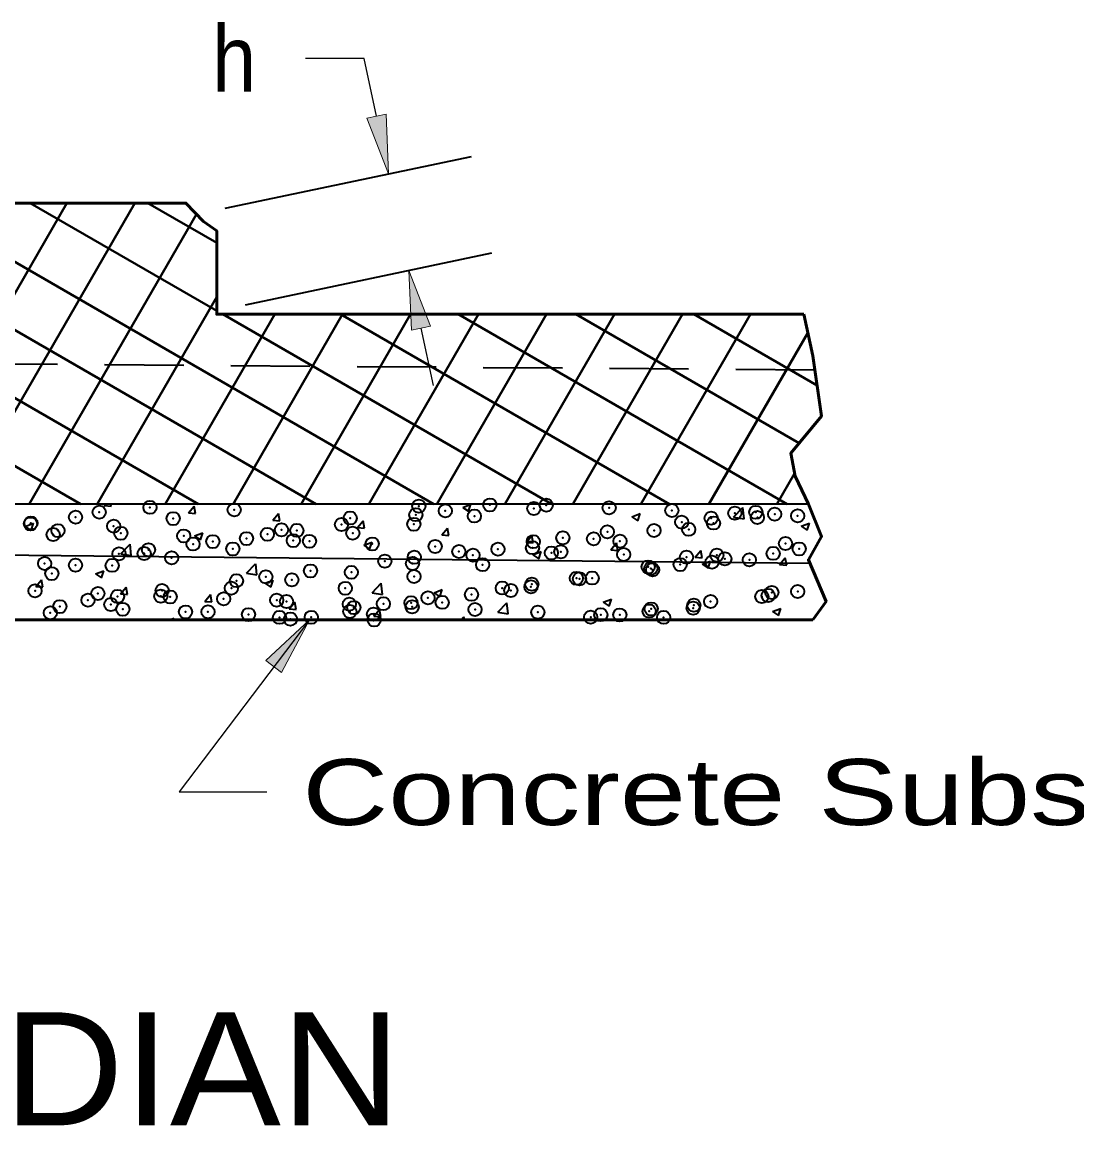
# Model space of a CAD drawing. Extents: x 14 to 49.3, y 28 to 50.
# Drawn here: x 22.139 to 24.379, y 39.449 to 41.795 of the extents above; entities that cross this region are included whole.
import ezdxf

# ---------------------------------------------------------------- set-up
doc = ezdxf.new("R2010")
doc.units = 0
doc.header["$LTSCALE"] = 0.056
doc.header["$PDMODE"] = 32
doc.header["$PDSIZE"] = 0.028
doc.linetypes.add('MEDIUM_DASHED', pattern=[4.5, 3, -1.5])
for name, color, linetype, lineweight in [('1', 7, 'Continuous', 35), ('2', 7, 'MEDIUM_DASHED', 35), ('3', 7, 'Continuous', 13), ('6', 7, 'Continuous', 13)]:
    doc.layers.add(name, color=color, linetype=linetype, lineweight=lineweight)

msp = doc.modelspace()

# ---------------------------------------------------------------- hatches: boundary and pattern name
at = {"layer": '1'}
for points in [[(22.87092, 41.59092), (22.91167, 41.5995), (22.917, 41.47283), (22.917, 41.47283)], [(22.9655, 41.14108), (23.00625, 41.14967), (22.96017, 41.26767), (22.96017, 41.26767)]]:
    msp.add_hatch(color=256, dxfattribs=at).paths.add_polyline_path(points)
at = {"layer": '3'}
msp.add_hatch(color=256, dxfattribs=at).paths.add_polyline_path([(22.65642, 40.43917), (22.68958, 40.41375), (22.749, 40.52558), (22.749, 40.52558)])

# ---------------------------------------------------------------- linework, layer by layer
at = {"layer": '1', "lineweight": 25}
for p, q in [((22.86558, 41.7175), (22.74058, 41.7175)), ((22.89125, 41.59517), (22.86558, 41.7175)), ((22.98583, 41.14533), (23.01158, 41.02308))]:
    msp.add_line(p, q, dxfattribs=at)
at = {"layer": '1'}
for p, q in [((22.57042, 41.4), (23.09317, 41.50992)), ((22.6135, 41.19483), (23.13625, 41.30475)), ((23.80842, 40.77142), (18.85933, 40.77142)), ((22.31292, 40.76875), (22.31517, 40.77142)), ((22.32783, 40.76742), (22.32708, 40.77142)), ((23.0745, 40.76458), (23.092, 40.77133)), ((23.08692, 40.75625), (23.092, 40.77133)), ((22.31292, 40.76875), (22.32783, 40.76742)), ((22.49217, 40.75308), (22.50425, 40.76742)), ((22.49217, 40.75308), (22.50717, 40.75175)), ((22.50717, 40.75175), (22.50425, 40.76742)), ((22.6715, 40.73742), (22.68358, 40.75175)), ((22.6865, 40.73608), (22.68358, 40.75175)), ((23.0745, 40.76458), (23.08692, 40.75625)), ((23.43375, 40.74458), (23.45125, 40.75133)), ((23.44617, 40.73617), (23.45125, 40.75133)), ((23.6495, 40.744), (23.669, 40.76433)), ((23.67175, 40.74058), (23.669, 40.76425)), ((22.14583, 40.724), (22.16333, 40.73075)), ((22.14583, 40.724), (22.15825, 40.71567)), ((22.15833, 40.71558), (22.16333, 40.73075)), ((22.6715, 40.73742), (22.68642, 40.73608)), ((22.85083, 40.72167), (22.86283, 40.73608)), ((22.86575, 40.72042), (22.86292, 40.73608)), ((23.43375, 40.74458), (23.44617, 40.73617)), ((23.6495, 40.744), (23.67175, 40.74058)), ((23.793, 40.72458), (23.8105, 40.73125)), ((23.793, 40.72458), (23.8055, 40.71617)), ((23.8055, 40.71617), (23.81058, 40.73125)), ((22.50517, 40.704), (22.52267, 40.71075)), ((22.50517, 40.704), (22.51758, 40.69558)), ((22.51758, 40.69558), (22.52267, 40.71067)), ((22.85083, 40.72167), (22.86575, 40.72042)), ((23.03017, 40.706), (23.04217, 40.72033)), ((23.03017, 40.706), (23.04508, 40.70467)), ((23.04508, 40.70467), (23.04217, 40.72033)), ((23.20942, 40.69033), (23.2215, 40.70467)), ((23.22442, 40.689), (23.2215, 40.70467)), ((23.81192, 40.64508), (18.81242, 40.69783)), ((22.34858, 40.666), (22.36808, 40.68625)), ((22.37083, 40.6625), (22.36808, 40.68625)), ((22.86442, 40.684), (22.88192, 40.69067)), ((22.86442, 40.684), (22.87683, 40.67558)), ((22.87683, 40.67558), (22.88192, 40.69067)), ((23.20942, 40.69033), (23.22442, 40.689)), ((23.20942, 40.69033), (23.22442, 40.689)), ((23.38875, 40.67467), (23.40083, 40.689)), ((23.40375, 40.67333), (23.40083, 40.689)), ((22.34858, 40.666), (22.37083, 40.66258)), ((23.22367, 40.66392), (23.24117, 40.67067)), ((23.22367, 40.66392), (23.23617, 40.65558)), ((23.23617, 40.65558), (23.24125, 40.67067)), ((23.38875, 40.67467), (23.40375, 40.67333)), ((23.56808, 40.65892), (23.58017, 40.67333)), ((23.56808, 40.65892), (23.583, 40.65767)), ((23.583, 40.65767), (23.58017, 40.67333)), ((23.74742, 40.64325), (23.75942, 40.65758)), ((23.76233, 40.64192), (23.75942, 40.65758)), ((22.29508, 40.62333), (22.31258, 40.63008)), ((22.3075, 40.615), (22.31258, 40.63008)), ((22.61542, 40.62458), (22.63483, 40.64492)), ((22.63767, 40.62117), (22.63492, 40.64492)), ((23.583, 40.64392), (23.6005, 40.65067)), ((23.583, 40.64392), (23.59542, 40.6355)), ((23.59542, 40.6355), (23.6005, 40.65067)), ((23.74742, 40.64325), (23.76233, 40.64192)), ((22.16825, 40.59642), (22.18033, 40.61075)), ((22.18317, 40.59508), (22.18033, 40.61075)), ((22.29508, 40.62333), (22.3075, 40.615)), ((22.61542, 40.62458), (22.63767, 40.62117)), ((22.65433, 40.60333), (22.67183, 40.61008)), ((22.66683, 40.59492), (22.67192, 40.61008)), ((22.16825, 40.59642), (22.18317, 40.59508)), ((22.34758, 40.58075), (22.35958, 40.59508)), ((22.3625, 40.57942), (22.35967, 40.59508)), ((22.65433, 40.60333), (22.66683, 40.59492)), ((22.65433, 40.60333), (22.66683, 40.59492)), ((22.88225, 40.58325), (22.90167, 40.6035)), ((22.88225, 40.58325), (22.90442, 40.57975)), ((22.90442, 40.57975), (22.90167, 40.6035)), ((23.01367, 40.58333), (23.03117, 40.59)), ((23.01367, 40.58333), (23.02608, 40.57492)), ((23.02608, 40.57492), (23.03117, 40.59)), ((22.34758, 40.58075), (22.3625, 40.57942)), ((22.52692, 40.565), (22.53892, 40.57942)), ((22.52692, 40.565), (22.54183, 40.56375)), ((22.54183, 40.56367), (22.53892, 40.57942)), ((22.70617, 40.54933), (22.71825, 40.56367)), ((22.72117, 40.548), (22.71825, 40.56367)), ((23.149, 40.54183), (23.1685, 40.56217)), ((23.17125, 40.53842), (23.1685, 40.56217)), ((23.37292, 40.56333), (23.39042, 40.57)), ((23.37292, 40.56333), (23.38533, 40.55492)), ((23.38533, 40.55492), (23.39042, 40.57)), ((22.70617, 40.54933), (22.72117, 40.548)), ((22.8855, 40.53367), (22.89758, 40.548)), ((22.9005, 40.53233), (22.89758, 40.548)), ((23.149, 40.54183), (23.17125, 40.53842)), ((23.73225, 40.54325), (23.74975, 40.55)), ((23.73225, 40.54325), (23.74467, 40.53492)), ((23.74467, 40.53492), (23.74975, 40.55)), ((22.45183, 40.52558), (22.46183, 40.52942)), ((22.4605, 40.52558), (22.46183, 40.52942)), ((22.8855, 40.53367), (22.90042, 40.53233)), ((23.07125, 40.52558), (23.07692, 40.53233)), ((23.07817, 40.52558), (23.07692, 40.53233))]:
    msp.add_line(p, q, dxfattribs=at)
at = {"layer": '1', "lineweight": 40}
for p, q in [((21.15617, 41.41067), (22.26342, 40.77142)), ((21.40617, 41.41067), (22.51342, 40.77142)), ((21.65617, 41.41067), (22.76342, 40.77142)), ((21.86508, 40.77142), (22.23417, 41.41067)), ((21.90617, 41.41067), (23.01342, 40.77142)), ((22.00942, 40.77142), (22.3785, 41.41067)), ((22.15617, 41.41067), (22.55233, 41.18192)), ((22.40617, 41.41067), (22.55233, 41.32633)), ((22.15375, 40.77142), (22.50925, 41.38708)), ((22.29808, 40.77142), (22.55233, 41.21183)), ((22.4425, 40.77142), (22.67525, 41.17467)), ((22.565, 41.17467), (23.26342, 40.77142)), ((22.58683, 40.77142), (22.81958, 41.17467)), ((22.73117, 40.77142), (22.96392, 41.17467)), ((22.815, 41.17467), (23.51342, 40.77142)), ((22.8755, 40.77142), (23.10825, 41.17467)), ((23.01983, 40.77142), (23.25258, 41.17467)), ((23.065, 41.17467), (23.76342, 40.77142)), ((23.16417, 40.77142), (23.39692, 41.17467)), ((23.3085, 40.77142), (23.54125, 41.17467)), ((23.315, 41.17467), (23.78883, 40.90108)), ((23.45283, 40.77142), (23.68558, 41.17467)), ((23.565, 41.17467), (23.82692, 41.02342)), ((23.59717, 40.77142), (23.80733, 41.13542)), ((23.7415, 40.77142), (23.77908, 40.83658))]:
    msp.add_line(p, q, dxfattribs=at)
at = {"layer": '1', "lineweight": 53}
msp.add_line((18.85933, 40.52558), (23.81775, 40.52558), dxfattribs=at)
at = {"layer": '1', "lineweight": 13}
for points in [[(22.87092, 41.59092), (22.91167, 41.5995), (22.917, 41.47283), (22.917, 41.47283)], [(22.9655, 41.14108), (23.00625, 41.14967), (22.96017, 41.26767), (22.96017, 41.26767)]]:
    msp.add_lwpolyline(points, close=True, dxfattribs=at)
at = {"layer": '1', "lineweight": 53}
for points in [[(23.799, 41.17467), (22.55233, 41.17467), (22.55233, 41.35167), (22.52425, 41.37133), (22.48675, 41.41067), (20.37783, 41.41067), (20.31217, 41.38117), (20.29342, 41.32217), (20.29342, 41.19433), (18.83125, 41.19433), (18.79375, 41.05667), (18.83125, 40.98783), (18.8125, 40.89933), (18.85933, 40.77142)], [(23.80842, 40.77142), (23.78025, 40.8305), (23.77092, 40.87967), (23.8365, 40.95833), (23.81775, 41.08617), (23.799, 41.17467)], [(23.81775, 40.52558), (23.84583, 40.56492), (23.80842, 40.65342), (23.8365, 40.70258), (23.80842, 40.77142)]]:
    msp.add_lwpolyline(points, dxfattribs=at)
at = {"layer": '1'}
for p in [(22.41042, 40.76458), (22.58942, 40.7595), (22.98142, 40.767), (23.0375, 40.75725), (23.13225, 40.76967), (23.2255, 40.76225), (23.25183, 40.76917), (23.38525, 40.7635), (23.51867, 40.75792), (22.2525, 40.74383), (22.30275, 40.75433), (22.45958, 40.74075), (22.83558, 40.74192), (22.97492, 40.749), (23.09925, 40.74625), (23.5395, 40.73333), (23.60208, 40.74158), (23.65217, 40.75225), (23.69675, 40.75408), (23.70008, 40.74292), (23.73683, 40.75008), (23.78558, 40.74658), (22.15692, 40.72933), (22.15783, 40.73133), (22.21517, 40.71517), (22.33333, 40.72475), (22.34858, 40.7095), (22.68975, 40.71692), (22.72233, 40.71575), (22.81708, 40.72817), (22.841, 40.70992), (22.97083, 40.72867), (23.38158, 40.71258), (23.48067, 40.71533), (23.55425, 40.71792), (23.60692, 40.73133), (22.20492, 40.70717), (22.48208, 40.70383), (22.50192, 40.68675), (22.544, 40.69192), (22.6155, 40.69825), (22.65975, 40.7075), (22.71475, 40.69392), (22.749, 40.69258), (22.88242, 40.68692), (23.22433, 40.69192), (23.28692, 40.70008), (23.35233, 40.69775), (23.40842, 40.69292), (23.75992, 40.688), (22.34467, 40.666), (22.39817, 40.66683), (22.40725, 40.67425), (22.58642, 40.67625), (23.01592, 40.68133), (23.06642, 40.67108), (23.09617, 40.663), (23.14933, 40.67567), (23.2225, 40.679), (23.26267, 40.66783), (23.28283, 40.67), (23.41625, 40.66442), (23.61417, 40.663), (23.73375, 40.66692), (23.78883, 40.67625), (22.18675, 40.64525), (22.25242, 40.64183), (22.33025, 40.6415), (22.4565, 40.65758), (22.90917, 40.65042), (22.96783, 40.64542), (22.97175, 40.65867), (23.11683, 40.64283), (23.53633, 40.643), (23.54975, 40.65875), (23.60392, 40.64817), (23.631, 40.6555), (23.68317, 40.65308), (22.20192, 40.62392), (22.65658, 40.61717), (22.75125, 40.62958), (22.838, 40.62667), (22.97108, 40.61783), (23.46833, 40.638), (23.47375, 40.63475), (23.47767, 40.63217), (22.58333, 40.59308), (22.594, 40.60892), (22.71167, 40.61067), (22.82525, 40.59275), (23.15858, 40.59325), (23.21942, 40.59583), (23.22117, 40.6015), (23.31583, 40.614), (23.32258, 40.613), (23.34925, 40.61458), (22.1665, 40.58742), (22.29992, 40.58175), (22.34142, 40.57567), (22.43342, 40.57608), (22.43617, 40.58808), (22.4535, 40.57433), (22.56683, 40.5705), (23.00067, 40.5725), (23.09317, 40.57983), (23.17675, 40.58792), (23.70967, 40.5755), (23.72308, 40.57767), (23.73075, 40.58367), (23.78567, 40.58592), (22.21917, 40.55383), (22.27883, 40.56742), (22.32725, 40.55833), (22.35267, 40.54817), (22.6795, 40.56775), (22.70033, 40.56483), (22.83375, 40.55917), (22.84342, 40.55175), (22.906, 40.56), (22.96475, 40.56217), (22.96717, 40.55358), (23.031, 40.56292), (23.10067, 40.54792), (23.47458, 40.54892), (23.56383, 40.5505), (23.56525, 40.55683), (23.60083, 40.56492), (22.19883, 40.54075), (22.48608, 40.5425), (22.53367, 40.54275), (22.61958, 40.53692), (22.6855, 40.531), (22.70867, 40.52742), (22.753, 40.53125), (22.83492, 40.54342), (22.88517, 40.53792), (22.8865, 40.52558), (23.23408, 40.54225), (23.34625, 40.53133), (23.36758, 40.53667), (23.40792, 40.53617), (23.4705, 40.54442), (23.501, 40.531)]:
    msp.add_point(p, dxfattribs=at)
at = {"layer": '2'}
msp.add_line((23.82217, 41.05592), (18.80383, 41.09367), dxfattribs=at)
at = {"layer": '3', "lineweight": 25}
for p, q in [((22.749, 40.52558), (22.47217, 40.16033)), ((22.47217, 40.16033), (22.65858, 40.16033))]:
    msp.add_line(p, q, dxfattribs=at)
at = {"layer": '3'}
msp.add_lwpolyline([(22.65642, 40.43917), (22.68958, 40.41375), (22.749, 40.52558), (22.749, 40.52558)], close=True, dxfattribs=at)
at = {"layer": '6', "lineweight": 25}
for p, q in [((22.917, 41.47283), (22.91708, 41.47283)), ((22.50925, 41.38708), (22.50933, 41.38708)), ((22.55233, 41.18192), (22.55242, 41.18192))]:
    msp.add_line(p, q, dxfattribs=at)

# ---------------------------------------------------------------- texts
at = {"layer": '1', "width": 0.9}
msp.add_text('h', height=0.14, dxfattribs=at).set_placement((22.54225, 41.6475))
at = {"layer": '3'}
for s, height, width, p in [('Concrete Subslab', 0.14, 1.35, (22.73392, 40.09017)), ('JOINT THRU MEDIAN', 0.24, 1.1, (19.37392, 39.45258))]:
    msp.add_text(s, height=height, dxfattribs=dict(at, width=width)).set_placement(p)

doc.saveas('drawing.dxf')
